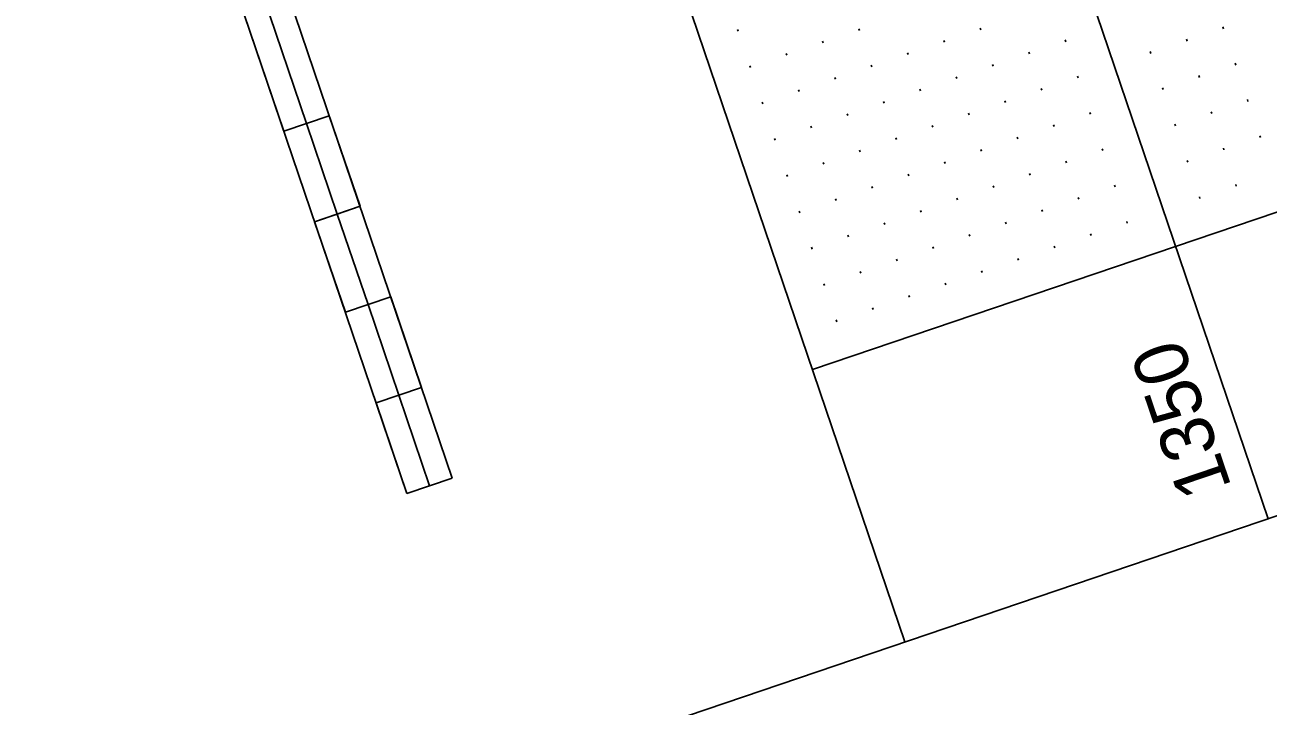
# Model space of a CAD drawing. Extents: x 2150800 to 2152547, y 141860 to 143950.
# Drawn here: x 2151773.3 to 2151935.4, y 142214 to 142302.8 of the extents above; entities that cross this region are included whole.
import ezdxf

# ---------------------------------------------------------------- set-up
doc = ezdxf.new("R2010")
doc.units = 0
for name, color, linetype in [('SHT_Plan_Profile_Sheet_Elev_Txt', 7, 'Continuous'), ('SHT_Profile_Grid_Major', 7, 'Continuous'), ('SHT_Profile_Grid_Minor', 7, 'Continuous'), ('SHT_Scale', 7, 'Continuous'), ('SHT_Sheet_Border', 7, 'Continuous')]:
    doc.layers.add(name, color=color, linetype=linetype)

msp = doc.modelspace()

# ---------------------------------------------------------------- linework, layer by layer
at = {"layer": 'SHT_Profile_Grid_Major'}
msp.add_line((2151935.36, 142238.42), (2151429.37, 143729.93), dxfattribs=at)
at = {"layer": 'SHT_Profile_Grid_Minor'}
for p, q in [((2151866.28, 142301.97), (2151866.2, 142302.21)), ((2151882.1, 142302.05), (2151882.02, 142302.29)), ((2151897.91, 142302.14), (2151897.83, 142302.37)), ((2151929.53, 142302.3), (2151929.45, 142302.54)), ((2151877.36, 142300.45), (2151877.28, 142300.68)), ((2151893.17, 142300.53), (2151893.09, 142300.77)), ((2151908.98, 142300.61), (2151908.9, 142300.85)), ((2151924.79, 142300.7), (2151924.71, 142300.93)), ((2151872.63, 142298.84), (2151872.55, 142299.08)), ((2151888.44, 142298.92), (2151888.36, 142299.16)), ((2151904.25, 142299.01), (2151904.17, 142299.24)), ((2151920.06, 142299.09), (2151919.98, 142299.33)), ((2151867.89, 142297.23), (2151867.81, 142297.47)), ((2151883.7, 142297.32), (2151883.62, 142297.55)), ((2151899.51, 142297.4), (2151899.43, 142297.64)), ((2151931.14, 142297.57), (2151931.06, 142297.81)), ((2151878.97, 142295.71), (2151878.89, 142295.95)), ((2151894.78, 142295.8), (2151894.7, 142296.03)), ((2151910.59, 142295.88), (2151910.51, 142296.12)), ((2151926.4, 142295.96), (2151926.32, 142296.2)), ((2151874.23, 142294.1), (2151874.15, 142294.34)), ((2151890.04, 142294.19), (2151889.96, 142294.43)), ((2151905.85, 142294.27), (2151905.77, 142294.51)), ((2151921.67, 142294.36), (2151921.59, 142294.59)), ((2151869.5, 142292.5), (2151869.42, 142292.74)), ((2151885.31, 142292.58), (2151885.23, 142292.82)), ((2151901.12, 142292.67), (2151901.04, 142292.9)), ((2151932.74, 142292.83), (2151932.66, 142293.07)), ((2151880.57, 142290.98), (2151880.49, 142291.21)), ((2151896.38, 142291.06), (2151896.3, 142291.3)), ((2151912.2, 142291.14), (2151912.12, 142291.38)), ((2151928.01, 142291.23), (2151927.93, 142291.47)), ((2151875.84, 142289.37), (2151875.76, 142289.61)), ((2151891.65, 142289.45), (2151891.57, 142289.69)), ((2151907.46, 142289.54), (2151907.38, 142289.77)), ((2151923.27, 142289.62), (2151923.19, 142289.86)), ((2151871.1, 142287.76), (2151871.02, 142288)), ((2151886.91, 142287.85), (2151886.83, 142288.08)), ((2151902.73, 142287.93), (2151902.65, 142288.17)), ((2151934.35, 142288.1), (2151934.27, 142288.34)), ((2151882.18, 142286.24), (2151882.1, 142286.48)), ((2151897.99, 142286.33), (2151897.91, 142286.56)), ((2151913.8, 142286.41), (2151913.72, 142286.65)), ((2151929.61, 142286.49), (2151929.53, 142286.73)), ((2151877.44, 142284.64), (2151877.36, 142284.87)), ((2151893.26, 142284.72), (2151893.18, 142284.96)), ((2151909.07, 142284.8), (2151908.99, 142285.04)), ((2151924.88, 142284.89), (2151924.8, 142285.12)), ((2151872.71, 142283.03), (2151872.63, 142283.27)), ((2151888.52, 142283.11), (2151888.44, 142283.35)), ((2151904.33, 142283.2), (2151904.25, 142283.43)), ((2151883.79, 142281.51), (2151883.71, 142281.74)), ((2151899.6, 142281.59), (2151899.52, 142281.83)), ((2151915.41, 142281.67), (2151915.33, 142281.91)), ((2151926.48, 142280.15), (2151926.4, 142280.39)), ((2151931.22, 142281.76), (2151931.14, 142282)), ((2151879.05, 142279.9), (2151878.97, 142280.14)), ((2151894.86, 142279.98), (2151894.78, 142280.22)), ((2151910.67, 142280.07), (2151910.59, 142280.3)), ((2151874.32, 142278.29), (2151874.24, 142278.53)), ((2151890.13, 142278.38), (2151890.05, 142278.61)), ((2151905.94, 142278.46), (2151905.86, 142278.7)), ((2151917.01, 142276.94), (2151916.93, 142277.18)), ((2151885.39, 142276.77), (2151885.31, 142277.01)), ((2151901.2, 142276.86), (2151901.12, 142277.09)), ((2151912.28, 142275.33), (2151912.2, 142275.57)), ((2151880.66, 142275.17), (2151880.58, 142275.4)), ((2151896.47, 142275.25), (2151896.39, 142275.49)), ((2151907.54, 142273.73), (2151907.46, 142273.96)), ((2151875.92, 142273.56), (2151875.84, 142273.8)), ((2151891.73, 142273.64), (2151891.65, 142273.88)), ((2151902.81, 142272.12), (2151902.73, 142272.36)), ((2151882.26, 142270.43), (2151882.18, 142270.67)), ((2151887, 142272.04), (2151886.92, 142272.27)), ((2151898.07, 142270.51), (2151897.99, 142270.75)), ((2151877.53, 142268.82), (2151877.45, 142269.06)), ((2151893.34, 142268.91), (2151893.26, 142269.14)), ((2151888.6, 142267.3), (2151888.52, 142267.54)), ((2151883.87, 142265.7), (2151883.79, 142265.93)), ((2151879.14, 142264.09), (2151879.05, 142264.33))]:
    msp.add_line(p, q, dxfattribs=at)
at = {"layer": 'SHT_Scale'}
for p, q in [((2151810.02, 142289.95), (2151777.97, 142384.42)), ((2151829, 142243.72), (2151780.93, 142385.42)), ((2151823.08, 142241.71), (2151775.01, 142383.41)), ((2151810.02, 142289.95), (2151793.99, 142337.18)), ((2151791.03, 142336.18), (2151807.06, 142288.95)), ((2151812.98, 142290.96), (2151810.02, 142289.95)), ((2151812.98, 142290.96), (2151810.02, 142289.95)), ((2151816.98, 142279.15), (2151812.98, 142290.96)), ((2151810.02, 142289.95), (2151807.06, 142288.95)), ((2151807.06, 142288.95), (2151810.02, 142289.95)), ((2151814.02, 142278.14), (2151810.02, 142289.95)), ((2151810.02, 142289.95), (2151814.02, 142278.14)), ((2151811.06, 142277.14), (2151816.98, 142279.15)), ((2151814.02, 142278.14), (2151816.98, 142279.15)), ((2151814.02, 142278.14), (2151811.06, 142277.14)), ((2151818.03, 142266.33), (2151814.02, 142278.14)), ((2151818.03, 142266.33), (2151814.02, 142278.14)), ((2151811.06, 142277.14), (2151815.07, 142265.33)), ((2151815.07, 142265.33), (2151820.99, 142267.34)), ((2151815.07, 142265.33), (2151820.99, 142267.34)), ((2151815.07, 142265.33), (2151818.03, 142266.33)), ((2151820.99, 142267.34), (2151818.03, 142266.33)), ((2151822.03, 142254.53), (2151818.03, 142266.33)), ((2151818.03, 142266.33), (2151822.03, 142254.53)), ((2151824.99, 142255.53), (2151820.99, 142267.34)), ((2151819.07, 142253.52), (2151824.99, 142255.53)), ((2151822.03, 142254.53), (2151819.07, 142253.52)), ((2151822.03, 142254.53), (2151824.99, 142255.53)), ((2151826.04, 142242.72), (2151822.03, 142254.53)), ((2151826.04, 142242.72), (2151822.03, 142254.53)), ((2151819.07, 142253.52), (2151823.08, 142241.71)), ((2151823.08, 142241.71), (2151829, 142243.72)), ((2151823.08, 142241.71), (2151826.04, 142242.72))]:
    msp.add_line(p, q, dxfattribs=at)
at = {"layer": 'SHT_Sheet_Border'}
for p, q in [((2151888.01, 142222.35), (2151382.02, 143713.86)), ((2152349.46, 142418.5), (2151875.97, 142257.87))]:
    msp.add_line(p, q, dxfattribs=at)
msp.add_lwpolyline([(2151383.74, 142051.28), (2150877.75, 143542.79), (2151872.09, 143880.12), (2152378.08, 142388.61)], close=True, dxfattribs=at)

# ---------------------------------------------------------------- texts
at = {"layer": 'SHT_Plan_Profile_Sheet_Elev_Txt'}
msp.add_text('1350', height=7, rotation=108.7393, dxfattribs=at).set_placement((2151930.64, 142242.51))

doc.saveas('drawing.dxf')
